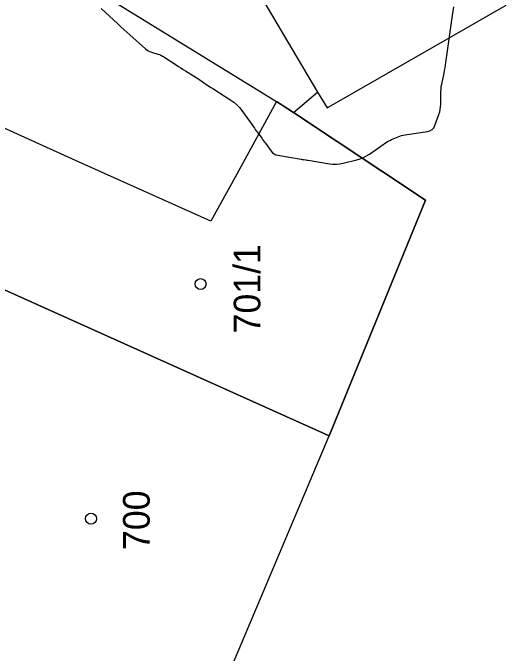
# Model space of a CAD drawing. Extents: x -534481 to -534256, y -1190577 to -1190138.
# Drawn here: x -534390.06 to -534374.33, y -1190397.49 to -1190377.09 of the extents above; entities that cross this region are included whole.
import ezdxf

# ---------------------------------------------------------------- set-up
doc = ezdxf.new("R2010")
doc.units = 0
for name, color, linetype in [('30', 7, 'Continuous'), ('Hranice parcel', 7, 'Continuous'), ('Parcelní čísla', 7, 'Continuous'), ('Polygon budovy', 7, 'Continuous'), ('Značky budov', 7, 'Continuous')]:
    doc.layers.add(name, color=color, linetype=linetype)

msp = doc.modelspace()

# ---------------------------------------------------------------- linework, layer by layer
at = {"layer": '30'}
msp.add_lwpolyline([(-534387.243, -1190376.949), (-534386.709, -1190377.445), (-534386.614, -1190377.533), (-534386.518, -1190377.62), (-534386.422, -1190377.706), (-534386.325, -1190377.792), (-534385.823, -1190378.236), (-534385.782, -1190378.269), (-534385.738, -1190378.297), (-534385.691, -1190378.321), (-534385.641, -1190378.339), (-534385.436, -1190378.403), (-534385.386, -1190378.421), (-534385.337, -1190378.442), (-534385.29, -1190378.466), (-534385.244, -1190378.494), (-534384.846, -1190378.75), (-534384.773, -1190378.797), (-534384.7, -1190378.844), (-534384.627, -1190378.891), (-534384.554, -1190378.937), (-534384.208, -1190379.155), (-534384.161, -1190379.185), (-534384.114, -1190379.216), (-534384.067, -1190379.246), (-534384.021, -1190379.277), (-534383.836, -1190379.403), (-534383.789, -1190379.434), (-534383.743, -1190379.465), (-534383.696, -1190379.495), (-534383.649, -1190379.525), (-534383.112, -1190379.869), (-534383.011, -1190379.94), (-534382.918, -1190380.02), (-534382.833, -1190380.109), (-534382.756, -1190380.206), (-534382.358, -1190380.764), (-534382.329, -1190380.804), (-534382.299, -1190380.844), (-534382.27, -1190380.885), (-534382.241, -1190380.925), (-534382.123, -1190381.085), (-534382.094, -1190381.125), (-534382.064, -1190381.166), (-534382.035, -1190381.206), (-534382.006, -1190381.246), (-534381.823, -1190381.496), (-534381.78, -1190381.546), (-534381.73, -1190381.584), (-534381.672, -1190381.612), (-534381.609, -1190381.629), (-534380.867, -1190381.751), (-534380.83, -1190381.758), (-534380.793, -1190381.764), (-534380.718, -1190381.776), (-534380.68, -1190381.782), (-534380.643, -1190381.788), (-534379.965, -1190381.902), (-534379.854, -1190381.915), (-534379.744, -1190381.916), (-534379.634, -1190381.906), (-534379.525, -1190381.884), (-534379.089, -1190381.772), (-534378.982, -1190381.74), (-534378.88, -1190381.698), (-534378.781, -1190381.648), (-534378.686, -1190381.589), (-534378.143, -1190381.214), (-534378.094, -1190381.183), (-534378.043, -1190381.154), (-534377.991, -1190381.128), (-534377.937, -1190381.106), (-534377.718, -1190381.021), (-534377.663, -1190381.002), (-534377.607, -1190380.986), (-534377.55, -1190380.973), (-534377.492, -1190380.963), (-534376.841, -1190380.87), (-534376.759, -1190380.848), (-534376.692, -1190380.809), (-534376.64, -1190380.751), (-534376.602, -1190380.676), (-534376.473, -1190380.324), (-534376.448, -1190380.247), (-534376.431, -1190380.169), (-534376.42, -1190380.089), (-534376.417, -1190380.008), (-534376.417, -1190379.681), (-534376.414, -1190379.6), (-534376.408, -1190379.519), (-534376.398, -1190379.438), (-534376.383, -1190379.358), (-534376.31, -1190379.013), (-534376.293, -1190378.929), (-534376.277, -1190378.844), (-534376.263, -1190378.759), (-534376.251, -1190378.674), (-534376.046, -1190377.175), (-534375.999, -1190376.898)], dxfattribs=at)
at = {"layer": 'Hranice parcel'}
for points in [[(-534389.87, -1190374.86), (-534381.65, -1190379.91), (-534381.11, -1190380.27)], [(-534381.11, -1190380.27), (-534380.34, -1190379.62), (-534380.04, -1190380.12), (-534376.63, -1190378.16), (-534374.33, -1190376.84)], [(-534381.11, -1190380.27), (-534376.9, -1190383.06), (-534379.97, -1190390.57)], [(-534379.97, -1190390.57), (-534392.22, -1190385.07), (-534396.64, -1190383.35), (-534396.74, -1190383.48), (-534396.92, -1190383.41), (-534402.36, -1190381.41)], [(-534397.83, -1190397.99), (-534392.73, -1190399.11), (-534384.27, -1190400.73), (-534379.97, -1190390.57)]]:
    msp.add_lwpolyline(points, dxfattribs=at)
at = {"layer": 'Polygon budovy'}
for points in [[(-534380.29, -1190367.33), (-534384.01, -1190370.07), (-534380.46, -1190374.87), (-534382.43, -1190376.09), (-534380.34, -1190379.62), (-534380.04, -1190380.12), (-534376.63, -1190378.16), (-534374.33, -1190376.84), (-534376.6, -1190372.66)], [(-534396.92, -1190383.41), (-534396.74, -1190383.48), (-534396.64, -1190383.35), (-534392.22, -1190385.07), (-534379.97, -1190390.57), (-534376.9, -1190383.06), (-534381.11, -1190380.27), (-534381.65, -1190379.91), (-534382.92, -1190382.23), (-534383.75, -1190383.73), (-534388.06, -1190381.79), (-534392.92, -1190379.6), (-534393.92, -1190381.89), (-534395.9, -1190381.05)], [(-534392.73, -1190399.11), (-534384.27, -1190400.73), (-534379.97, -1190390.57), (-534392.22, -1190385.07), (-534395.24, -1190392.02), (-534390.48, -1190393.97)]]:
    msp.add_lwpolyline(points, close=True, dxfattribs=at)
at = {"layer": 'Značky budov'}
for centre in [(-534384.072, -1190385.732), (-534387.566, -1190393.206)]:
    msp.add_circle(centre, 0.175, dxfattribs=at)

# ---------------------------------------------------------------- texts
at = {"layer": 'Parcelní čísla'}
for s, p in [('701/1', (-534382.165, -1190387.303)), ('700', (-534385.694, -1190394.205))]:
    msp.add_text(s, height=0.85, rotation=90, dxfattribs=at).set_placement(p)

doc.saveas('drawing.dxf')
